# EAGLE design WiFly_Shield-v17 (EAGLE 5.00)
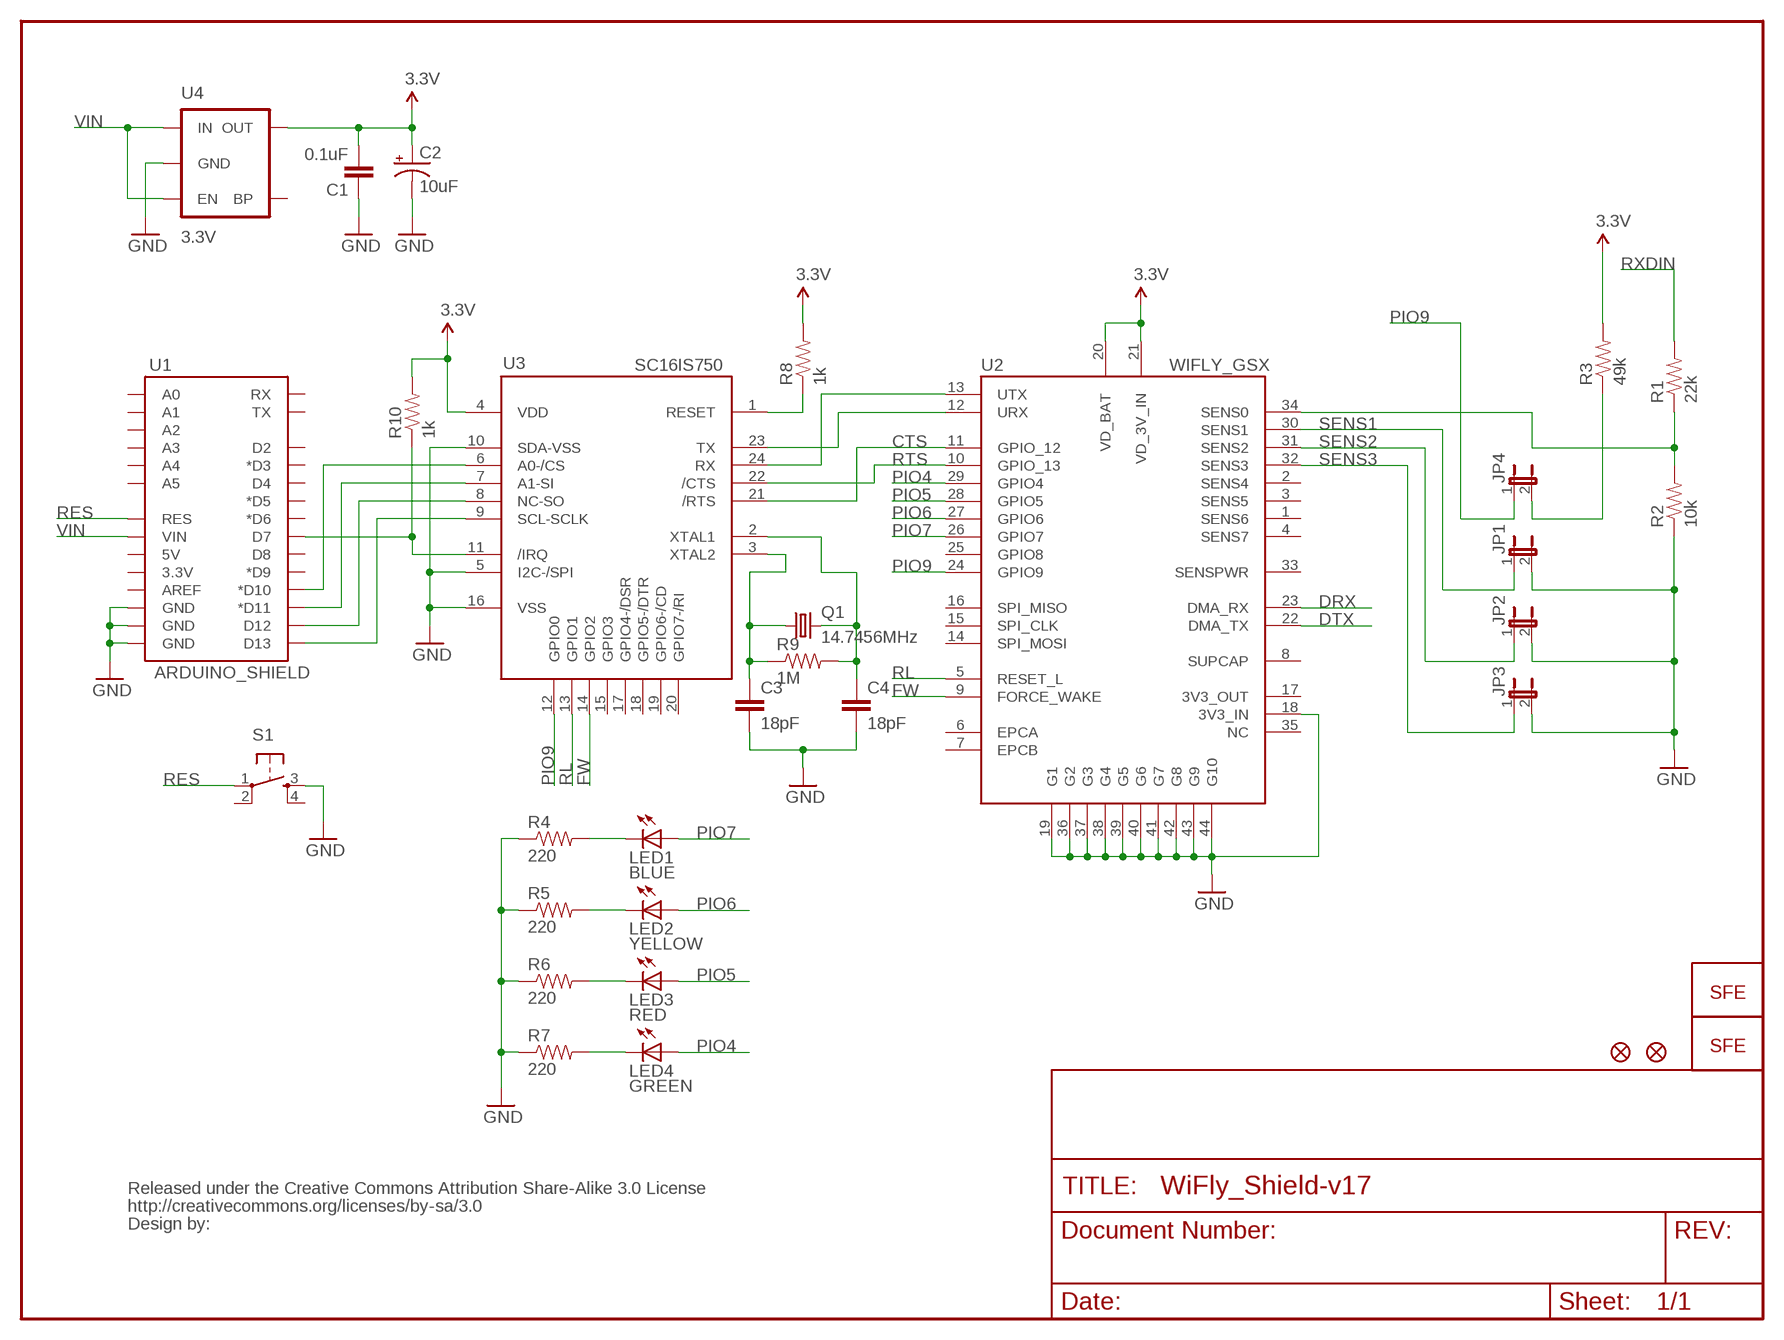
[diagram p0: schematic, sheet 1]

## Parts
C1  0.1uF  CAP0402-CAP  [0402-CAP]
C2  10uF  CAP_POL1206  [EIA3216]
C3  18pF  CAP0402-CAP  [0402-CAP]
C4  18pF  CAP0402-CAP  [0402-CAP]
JP1  JUMPER-2SMD-NO  [SJ_2S-NO]
JP2  JUMPER-2SMD-NO  [SJ_2S-NO]
JP3  JUMPER-2SMD-NO  [SJ_2S-NO]
JP4  JUMPER-2SMD-NO  [SJ_2S-NO]
JP6  LOGO-SFENEW  [SFE-NEW-WEBLOGO]
JP7  FIDUCIAL1X2  [FIDUCIAL-1X2]
JP8  FIDUCIAL1X2  [FIDUCIAL-1X2]
JP9  LOGO-SFESK  [SFE-LOGO-FLAME]
LED1  BLUE  LED0603  [LED-0603]
LED2  YELLOW  LED0603  [LED-0603]
LED3  RED  LED0603  [LED-0603]
LED4  GREEN  LED0603  [LED-0603]
Q1  14.7456MHz  CRYSTAL5X3  [CRYSTAL-SMD-5X3]
R1  22k  RESISTOR0402-RES  [0402-RES]
R2  10k  RESISTOR0402-RES  [0402-RES]
R3  49k  RESISTOR0402-RES  [0402-RES]
R4  220  RESISTOR0402-RES  [0402-RES]
R5  220  RESISTOR0402-RES  [0402-RES]
R6  220  RESISTOR0402-RES  [0402-RES]
R7  220  RESISTOR0402-RES  [0402-RES]
R8  1k  RESISTOR0402-RES  [0402-RES]
R9  1M  RESISTOR0402-RES  [0402-RES]
R10  1k  RESISTOR0402-RES  [0402-RES]
S1  TAC_SWITCHSMD  [TACTILE_SWITCH_SMD]
U1  ARDUINO_SHIELD  ARDUINO_SHIELDLABEL  [DUEMILANOVE_SHIELD]
U2  WIFLY_GSX  [WIFLY_GSX]
U3  SC16IS750  [QFN-24]
U4  3.3V  V_REG_LDOSMD  [SOT23-5]
U$1  CREATIVE_COMMONS  [CREATIVE_COMMONS]

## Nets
3.3V: C1.2 C2.A(+) R3.2 R8.2 R10.2 U2.20(VD_BAT) U2.21(VD_3V_IN) U3.4(VDD) U4.5(OUT)
CTS: U2.11(GPIO_12) U3.21(/RTS)
DRX: U2.23(DMA_RX)
DTX: U2.22(DMA_TX)
FW: U2.9(FORCE_WAKE) U3.14(GPIO2)
GND: C1.1 C2.C(-) C3.2 C4.2 JP1.2 JP2.2 JP3.2 R2.1 R4.1 R5.1 R6.1 R7.1 S1.3 U1.GND@0(GND) U1.GND@1(GND) U1.GND@2(GND) U2.18(3V3_IN) U2.19(G1) U2.36(G2) U2.37(G3) U2.38(G4) U2.39(G5) U2.40(G6) U2.41(G7) U2.42(G8) U2.43(G9) U2.44(G10) U3.5(I2C-/SPI) U3.10(SDA-VSS) U3.16(VSS) U4.2(GND)
N$1: LED4.C R7.2
N$2: JP4.2 R3.1
N$3: LED3.C R6.2
N$4: LED2.C R5.2
N$5: LED1.C R4.2
N$6: U2.13(UTX) U3.24(RX)
N$7: U2.12(URX) U3.23(TX)
N$8: U1.D10(*D10) U3.6(A0-/CS)
N$9: R8.1 U3.1(RESET)
N$10: U1.D11(*D11) U3.7(A1-SI)
N$11: C3.1 Q1.1 R9.1 U3.3(XTAL2)
N$12: C4.1 Q1.3 R9.2 U3.2(XTAL1)
N$13: U1.D12 U3.8(NC-SO)
N$14: U1.D13 U3.9(SCL-SCLK)
N$16: R1.1 R2.2 U2.34(SENS0)
N$154: R10.1 U1.D7 U3.11(/IRQ)
PIO4: LED4.A U2.29(GPIO4)
PIO5: LED3.A U2.28(GPIO5)
PIO6: LED2.A U2.27(GPIO6)
PIO7: LED1.A U2.26(GPIO7)
PIO9: JP4.1 U2.24(GPIO9) U3.12(GPIO0)
RES: S1.1 U1.RES
RL: U2.5(RESET_L) U3.13(GPIO1)
RTS: U2.10(GPIO_13) U3.22(/CTS)
RXDIN: R1.2
SENS1: JP1.1 U2.30(SENS1)
SENS2: JP2.1 U2.31(SENS2)
SENS3: JP3.1 U2.32(SENS3)
VIN: U1.VIN U4.1(IN) U4.3(EN)
Unconnected: S1.2 S1.4 U1.3.3V U1.5V U1.A0 U1.A1 U1.A2 U1.A3 U1.A4 U1.A5 U1.AREF U1.D2 U1.D3(*D3) U1.D4 U1.D5(*D5) U1.D6(*D6) U1.D8 U1.D9(*D9) U1.RX U1.TX U2.1(SENS6) U2.2(SENS4) U2.3(SENS5) U2.4(SENS7) U2.6(EPCA) U2.7(EPCB) U2.8(SUPCAP) U2.14(SPI_MOSI) U2.15(SPI_CLK) U2.16(SPI_MISO) U2.17(3V3_OUT) U2.25(GPIO8) U2.33(SENSPWR) U2.35(NC) U3.15(GPIO3) U3.17(GPIO4-/DSR) U3.18(GPIO5-/DTR) U3.19(GPIO6-/CD) U3.20(GPIO7-/RI) U4.4(BP)

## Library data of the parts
C1 C3 C4 = SparkFun:CAP: Capacitor
C2 = SparkFun:CAP_POL: Capacitor Polarized
JP1-JP4 = SparkFun:JUMPER-2: Jumper
JP6 JP9 = SparkFun:LOGO-SFE: Spark Fun Electronics PCB Logo
JP7 JP8 = SparkFun:FIDUCIAL: Fiducial Alignment Points
LED1-LED4 = SparkFun:LED: LEDs
Q1 = SparkFun:CRYSTAL: Crystals
R1-R10 = SparkFun:RESISTOR: Resistor
S1 = SparkFun:TAC_SWITCH: Momentary Switch Button commonly used for reset or general input. Spark Fun Electronics SKU : COM-00097
U1 = SparkFun:ARDUINO_SHIELD
U2 = SparkFun:WIFLY_GSX
U3 = SparkFun:SC16IS750
U4 = SparkFun:V_REG_LDO: Voltage Regulator LDO Standard 150mA LDO voltage regulator in SOT-23 layout. Micrel part MIC5205. BP (by-pass) pin is used to lower output noise with 470pF cap.
U$1 = SparkFun:CREATIVE_COMMONS

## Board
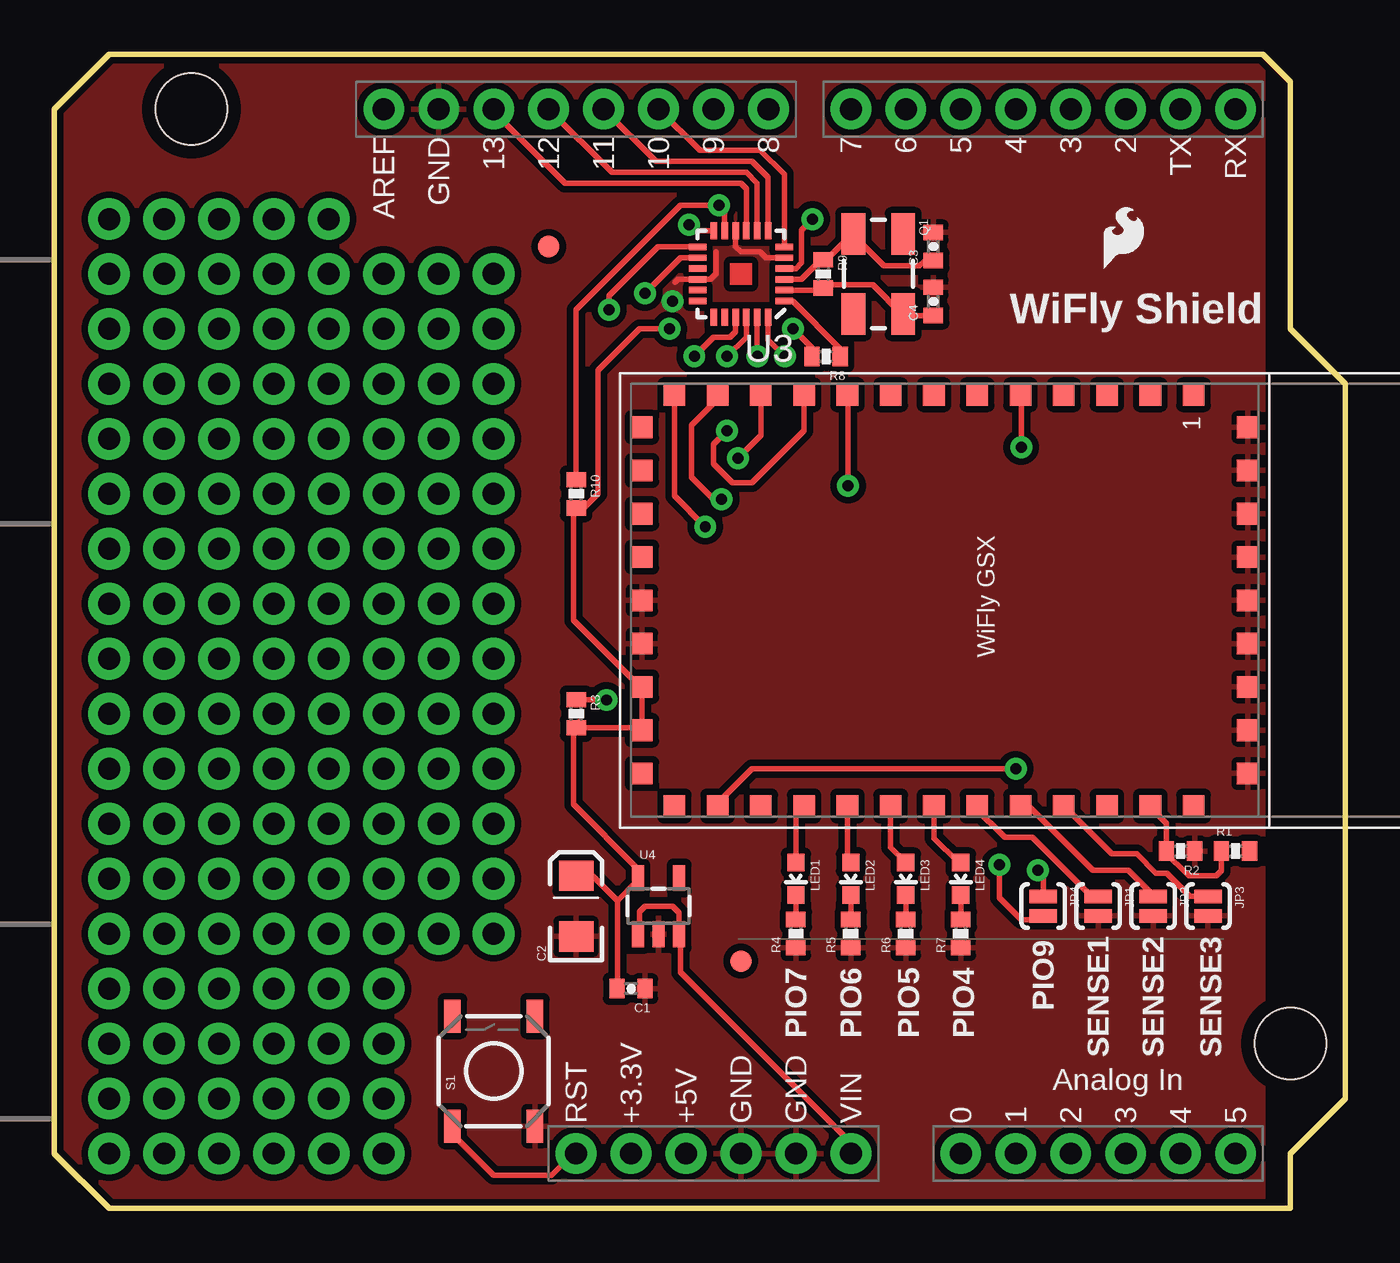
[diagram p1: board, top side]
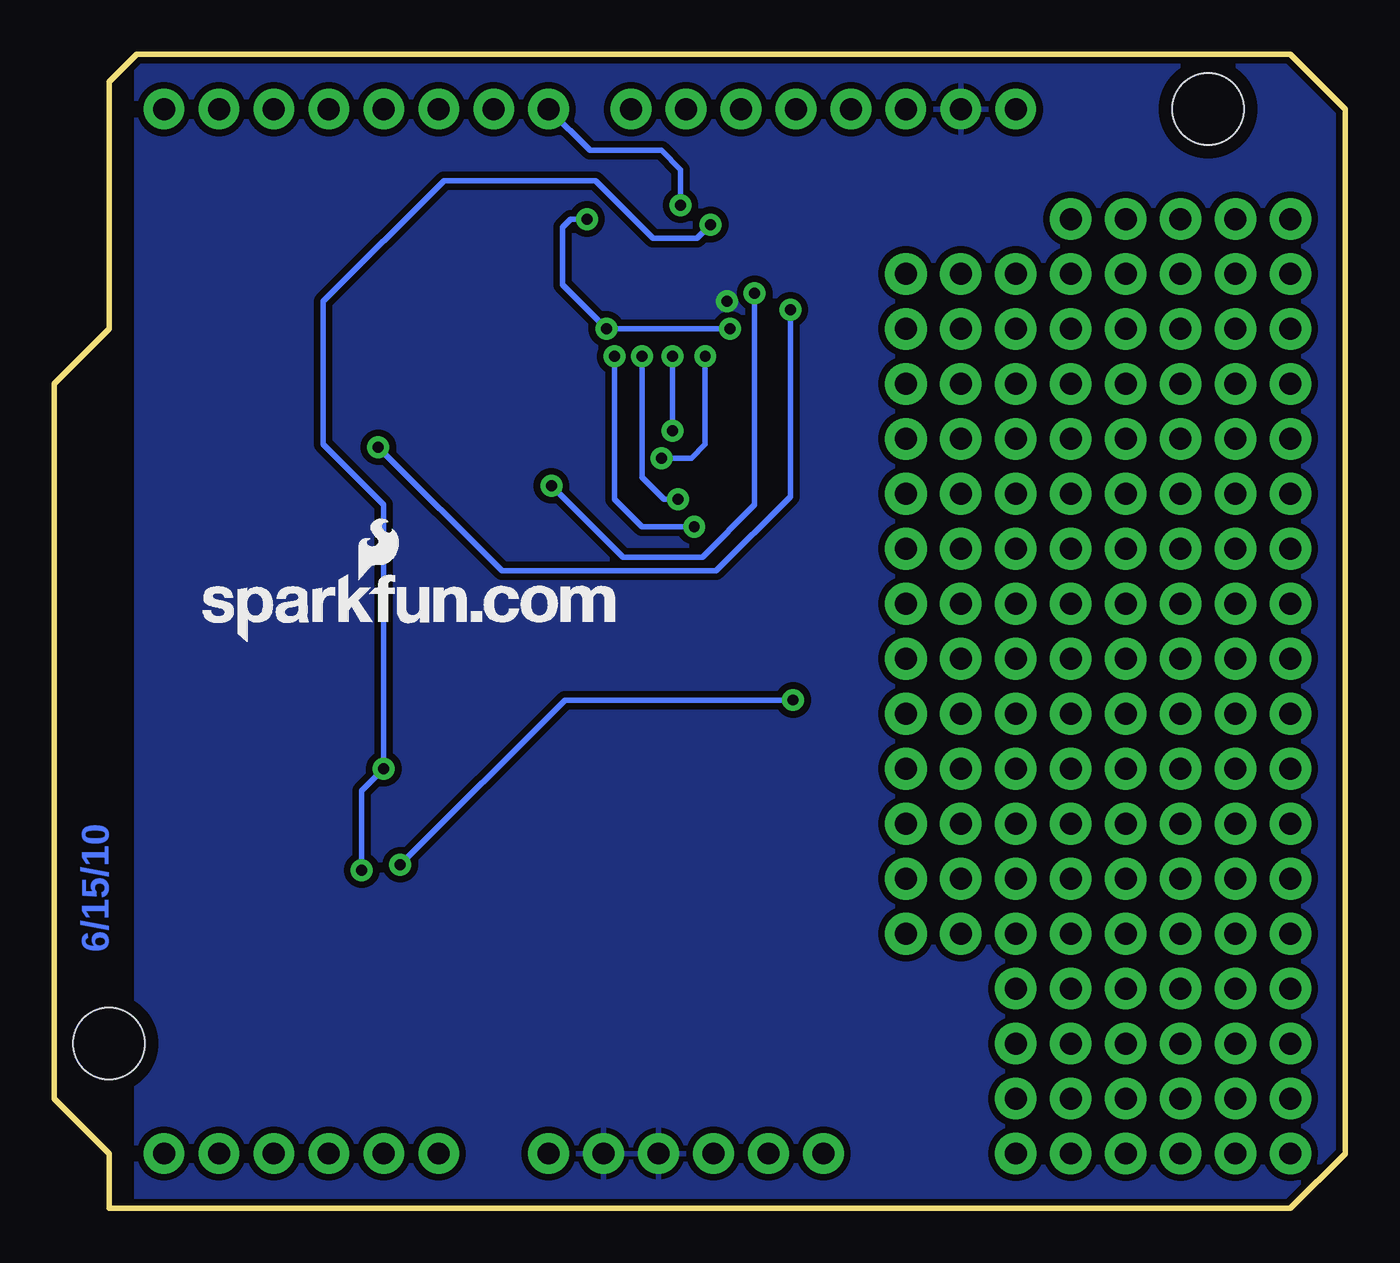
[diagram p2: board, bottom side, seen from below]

Size 59.69 x 53.34 mm. Coordinates in mm from the lower left corner, seen from the top.
Outline: 2.54,53.34 55.88,53.34 57.15,52.07 57.15,40.64 59.69,38.1 59.69,5.08 57.15,2.54 57.15,0 2.54,0 0,2.54 0,50.8 2.54,53.34
Copper layers (1*16): Top 0.035mm / dielectric 1.5mm / Bottom 0.035mm
Design rules "SparkFun *": minimum track width 8mil, minimum drill 20mil, track to track 8mil, track to pad 8mil, pad to pad 7mil, via to via 8mil, smd to smd 8mil, copper to edge 10mil, drill to drill 8mil, minimum pad ring 12mil, minimum via ring 10mil, stop-mask expansion 4mil, vias tented up to drill 25mil, thermal gap 10mil

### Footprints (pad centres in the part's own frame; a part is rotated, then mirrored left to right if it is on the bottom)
0402-CAP = smd 0.7 x 0.9: 1 -0.65,0; 2 0.65,0
EIA3216 = smd 1.4 x 1.6: A 1.4,0; C -1.4,0
SJ_2S-NO = smd 0.635 x 1.27: 1 -0.45,0; 2 0.45,0
FIDUCIAL-1X2 = smd 1 x 1: 1 0,0
LED-0603 = smd 0.8 x 0.8: A 0,-0.75; C 0,0.75
CRYSTAL-SMD-5X3 = smd 1.9 x 1.1: 1 -1.85,-1.15; 2 1.85,-1.15; 3 1.85,1.15; 4 -1.85,1.15
0402-RES = smd 0.7 x 0.9: 1 -0.65,0; 2 0.65,0
TACTILE_SWITCH_SMD = smd 1.524 x 0.762: 1 -2.54,1.905; 2 2.54,1.905; 3 -2.54,-1.905; 4 2.54,-1.905
DUEMILANOVE_SHIELD = drill 1.016 pad 1.88 round: 3.3V 50.8,26.67; 5V 50.8,29.21; A0 50.8,41.91; A1 50.8,44.45; A2 50.8,46.99; A3 50.8,49.53; A4 50.8,52.07; A5 50.8,54.61; AREF 2.54,15.24; D2 2.54,49.53; D3 2.54,46.99; D4 2.54,44.45; D5 2.54,41.91; D6 2.54,39.37; D7 2.54,36.83; D8 2.54,33.02; D9 2.54,30.48; D10 2.54,27.94; D11 2.54,25.4; D12 2.54,22.86; D13 2.54,20.32; GND@0 50.8,31.75; GND@1 50.8,34.29; GND@2 2.54,17.78; RES 50.8,24.13; RX 2.54,54.61; TX 2.54,52.07; VIN 50.8,36.83 | hole 3.302: 45.72,57.15; 2.54,6.35
WIFLY_GSX = smd 1 x 1: 1 0.5,26; 2 0.5,24; 3 0.5,22; 4 0.5,20; 5 0.5,18; 6 0.5,16; 7 0.5,14; 8 0.5,12; 9 0.5,10; 10 0.5,8; 11 0.5,6; 12 0.5,4; 13 0.5,2; 14 2,0.5; 15 4,0.5; 16 6,0.5; 17 8,0.5; 18 10,0.5; 19 12,0.5; 20 14,0.5; 21 16,0.5; 22 18,0.5; 23 19.5,2; 24 19.5,4; 25 19.5,6; 26 19.5,8; 27 19.5,10; 28 19.5,12; 29 19.5,14; 30 19.5,16; 31 19.5,18; 32 19.5,20; 33 19.5,22; 34 19.5,24; 35 19.5,26; 36 18,28.5; 37 16,28.5; 38 14,28.5; 39 12,28.5; 40 10,28.5; 41 8,28.5; 42 6,28.5; 43 4,28.5; 44 2,28.5
QFN-24 = smd 0.8 x 0.3: 1 -2,1.25; 2 -2,0.75; 3 -2,0.25; 4 -2,-0.25; 5 -2,-0.75; 6 -2,-1.25; 13 2,-1.25; 14 2,-0.75; 15 2,-0.25; 16 2,0.25; 17 2,0.75; 18 2,1.25 | smd 0.3 x 0.8: 7 -1.25,-2; 8 -0.75,-2; 9 -0.25,-2; 10 0.25,-2; 11 0.75,-2; 12 1.25,-2; 19 1.25,2; 20 0.75,2; 21 0.25,2; 22 -0.25,2; 23 -0.75,2; 24 -1.25,2
SOT23-5 = smd 0.55 x 1.2: 1 -0.95,-1.3; 2 0,-1.3; 3 0.95,-1.3; 4 0.95,1.3; 5 -0.95,1.3

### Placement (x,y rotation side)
C1  26.67,10.16 180 top
C2  24.13,13.97 90 top
C3  40.64,44.45 90 top
C4  40.64,41.91 90 top
JP1  48.26,13.97 270 top
JP2  50.8,13.97 270 top
JP3  53.34,13.97 270 top
JP4  45.72,13.97 270 top
JP6  52.83,26.16 0 bottom
JP7  31.75,11.43 0 top
JP8  22.86,44.45 0 top
JP9  48.51,43.43 0 top
LED1  34.29,15.24 180 top
LED2  36.83,15.24 180 top
LED3  39.37,15.24 180 top
LED4  41.91,15.24 180 top
Q1  38.1,43.18 270 top
R1  54.61,16.51 0 top
R2  52.07,16.51 180 top
R3  24.13,22.86 270 top
R4  34.29,12.7 90 top
R5  36.83,12.7 90 top
R6  39.37,12.7 90 top
R7  41.91,12.7 90 top
R8  35.69,39.37 180 top
R9  35.56,43.18 270 top
R10  24.13,33.02 270 top
S1  20.32,6.35 90 top
U1  0,53.34 270 top
U2  26.67,38.1 270 top
U3  31.75,43.18 180 top
U4  27.94,13.97 0 top
U$1  not placed on the board

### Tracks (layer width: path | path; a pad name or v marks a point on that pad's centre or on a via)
3.3V  (via drill 0.51)
  Top 0.254: 27.11,22.16 27.07,22.21 24.37,22.21 24.26,22.1 24.14,22.21 R3.2 24.13,22.1 24,22.1 | 27.11,22.16 U2.21 | 24,22.1 24,18.67 26.99,15.68 26.99,15.31 26.95,15.27 | 24,22.1 24,22.23 24.26,22.48 | 27.3,22.1 | 27.3,22.1 U2.21 27.17,22.22 | 27.18,22.23 27.3,22.1 | 27.18,22.23 27.17,22.23 U2.20 27.17,24.12 | v34.16,40.64 35.04,39.77 35.04,39.38 35.05,39.37 R8.2 | v35.05,45.72 34.54,45.21 34.54,43.69 34.29,43.43 33.79,43.43 33.78,43.43 U3.4 | 24.14,32.37 24.13,32.38 24,32.26 24,27.18 27.08,24.1 27.15,24.1 27.17,24.12 | 24.14,32.37 24.5,32.37 25.15,33.02 25.15,38.73 27.05,40.64 v28.45,40.64 | 27.17,24.12 27.18,24.13 | C1.2 26.04,10.18 26.04,14.22 | 26.92,15.24 26.96,15.24 U4.5 26.95,15.27 | 26.04,14.22 26.92,15.11 26.92,15.24 | C2.A 24.89,15.37 26.04,14.22 | 26.92,15.24 26.95,15.27 | 27.11,22.16 27.17,22.22 | 27.17,22.22 27.18,22.23 | R10.2 24.13,32.26 24.14,32.27 24.14,32.37
  Bottom 0.254: v35.05,45.72 35.81,45.72 36.2,45.34 36.2,42.67 v34.16,40.64 v28.45,40.64
CTS  (via drill 0.51)
  Top 0.254: U3.21 31.5,40.52 31.24,40.26 30.48,40.26 v29.59,39.37 | U2.11 32.67,35.72 v31.62,34.67
  Bottom 0.254: v31.62,34.67 30.23,34.67 29.59,35.31 v29.59,39.37
FW  (via drill 0.51)
  Top 0.254: U3.14 28.94,43.93 v27.3,42.29 | v36.7,33.4 36.7,37.57 U2.9
  Bottom 0.254: v27.3,42.29 27.3,32.51 29.72,30.1 33.4,30.1 v36.7,33.4
GND  (via drill 0.51)
  Top 0.254: 30.61,44.2 30.61,43.18 30.35,42.93 29.84,42.93 U3.16 28.83,42.93 28.7,42.8 | U3.5 32.91,43.93 32.64,44.2 31.75,44.2 31.5,44.45 U3.10
  other vias: 28.57,41.91
  pour Bottom (isolate 0.305): 2.54,53.34 55.88,53.34 55.88,0 2.54,0 0,2.54 0,50.8
  pour Top (isolate 0.305): 2.54,53.34 55.88,53.34 55.88,0 2.54,0 0,2.54 0,50.8
N$1
  Top 0.254: 41.91,14.61 LED4.C R7.2
N$2  (via drill 0.51)
  Top 0.254: R3.1 25.51,23.51 v25.53,23.5 | v43.69,15.88 43.69,14.35 44.7,13.34 45.47,13.34 45.65,13.52 JP4.2
  Bottom 0.254: v25.53,23.5 36.07,23.5 v43.69,15.88
N$3
  Top 0.254: 39.37,14.61 LED3.C R6.2
N$4
  Top 0.254: 36.83,14.61 LED2.C R5.2
N$5
  Top 0.254: R4.2 LED1.C
N$6  (via drill 0.51)
  Top 0.254: U3.24 33,40.15 v33.78,39.37 | U2.13 28.67,32.92 v30.1,31.5
  Bottom 0.254: v30.1,31.5 32.51,31.5 33.78,32.77 v33.78,39.37
N$7  (via drill 0.51)
  Top 0.254: U3.23 32.5,39.89 v32.51,39.37 | U2.12 30.67,37.4 29.46,36.2 29.46,33.78 30.48,32.77 v30.86,32.77
  Bottom 0.254: v30.86,32.77 31.5,32.77 32.51,33.78 v32.51,39.37
N$8
  Top 0.254: U1.D10 29.84,48.9 32.64,48.9 33.75,47.78 U3.6
N$9
  Top 0.254: R8.1 36.34,39.74 34.14,41.93 U3.1
N$10
  Top 0.254: U3.7 33,47.65 32.26,48.39 27.81,48.39 U1.D11
N$11
  Top 0.254: C3.1 40.24,43.8 40.01,43.56 38.35,43.56 36.95,44.97 | 36.95,44.97 Q1.1 | 36.95,44.97 36.84,44.97 35.69,43.81 35.67,43.83 R9.1 35.45,43.83 34.55,42.93 U3.3
N$12
  Top 0.254: C4.1 39.38,41.26 39.31,41.33 Q1.3 39.19,41.33 37.85,42.67 35.81,42.67 35.56,42.42 R9.2 35.56,42.55 35.45,42.43 U3.2
N$13
  Top 0.254: U3.8 32.5,47.38 32,47.88 25.78,47.88 U1.D12
N$14
  Top 0.254: U3.9 32,47.12 31.75,47.37 23.62,47.37 20.32,50.67 U1.D13
N$15  (via drill 1.02 pad 1.93)
  other vias: 5.08,2.54
N$16
  Top 0.254: U2.34 50.67,18.55 51.42,17.8 R2.2 51.31,16.51 52.45,15.37 53.72,15.37 53.96,15.61 R1.1
N$17  (via drill 1.02 pad 1.93)
  other vias: 7.62,2.54
N$18  (via drill 1.02 pad 1.93)
  other vias: 10.16,2.54
N$19  (via drill 1.02 pad 1.93)
  other vias: 12.7,2.54
N$20  (via drill 1.02 pad 1.93)
  other vias: 15.24,2.54
N$23  (via drill 1.02 pad 1.93)
  other vias: 2.54,2.54
N$24  (via drill 1.02 pad 1.93)
  other vias: 5.08,5.08
N$25  (via drill 1.02 pad 1.93)
  other vias: 7.62,5.08
N$26  (via drill 1.02 pad 1.93)
  other vias: 10.16,5.08
N$27  (via drill 1.02 pad 1.93)
  other vias: 12.7,5.08
N$28  (via drill 1.02 pad 1.93)
  other vias: 15.24,5.08
N$31  (via drill 1.02 pad 1.93)
  other vias: 2.54,5.08
N$32  (via drill 1.02 pad 1.93)
  other vias: 5.08,7.62
N$33  (via drill 1.02 pad 1.93)
  other vias: 7.62,7.62
N$34  (via drill 1.02 pad 1.93)
  other vias: 10.16,7.62
N$35  (via drill 1.02 pad 1.93)
  other vias: 12.7,7.62
N$36  (via drill 1.02 pad 1.93)
  other vias: 15.24,7.62
N$39  (via drill 1.02 pad 1.93)
  other vias: 2.54,7.62
N$40  (via drill 1.02 pad 1.93)
  other vias: 5.08,10.16
N$41  (via drill 1.02 pad 1.93)
  other vias: 7.62,10.16
N$42  (via drill 1.02 pad 1.93)
  other vias: 10.16,10.16
N$43  (via drill 1.02 pad 1.93)
  other vias: 12.7,10.16
N$44  (via drill 1.02 pad 1.93)
  other vias: 15.24,10.16
N$47  (via drill 1.02 pad 1.93)
  other vias: 2.54,10.16
N$48  (via drill 1.02 pad 1.93)
  other vias: 5.08,12.7
N$49  (via drill 1.02 pad 1.93)
  other vias: 7.62,12.7
N$50  (via drill 1.02 pad 1.93)
  other vias: 10.16,12.7
N$51  (via drill 1.02 pad 1.93)
  other vias: 12.7,12.7
N$52  (via drill 1.02 pad 1.93)
  other vias: 15.24,12.7
N$53  (via drill 1.02 pad 1.93)
  other vias: 17.78,12.7
N$54  (via drill 1.02 pad 1.93)
  other vias: 20.32,12.7
N$55  (via drill 1.02 pad 1.93)
  other vias: 2.54,12.7
N$56  (via drill 1.02 pad 1.93)
  other vias: 5.08,15.24
N$57  (via drill 1.02 pad 1.93)
  other vias: 7.62,15.24
N$58  (via drill 1.02 pad 1.93)
  other vias: 10.16,15.24
N$59  (via drill 1.02 pad 1.93)
  other vias: 12.7,15.24
N$60  (via drill 1.02 pad 1.93)
  other vias: 15.24,15.24
N$61  (via drill 1.02 pad 1.93)
  other vias: 17.78,15.24
N$62  (via drill 1.02 pad 1.93)
  other vias: 20.32,15.24
N$63  (via drill 1.02 pad 1.93)
  other vias: 2.54,15.24
N$64  (via drill 1.02 pad 1.93)
  other vias: 5.08,17.78
N$65  (via drill 1.02 pad 1.93)
  other vias: 7.62,17.78
N$66  (via drill 1.02 pad 1.93)
  other vias: 10.16,17.78
N$67  (via drill 1.02 pad 1.93)
  other vias: 12.7,17.78
N$68  (via drill 1.02 pad 1.93)
  other vias: 15.24,17.78
N$69  (via drill 1.02 pad 1.93)
  other vias: 17.78,17.78
N$70  (via drill 1.02 pad 1.93)
  other vias: 20.32,17.78
N$71  (via drill 1.02 pad 1.93)
  other vias: 2.54,17.78
N$72  (via drill 1.02 pad 1.93)
  other vias: 5.08,20.32
N$73  (via drill 1.02 pad 1.93)
  other vias: 7.62,20.32
N$74  (via drill 1.02 pad 1.93)
  other vias: 10.16,20.32
N$75  (via drill 1.02 pad 1.93)
  other vias: 12.7,20.32
N$76  (via drill 1.02 pad 1.93)
  other vias: 15.24,20.32
N$77  (via drill 1.02 pad 1.93)
  other vias: 17.78,20.32
N$78  (via drill 1.02 pad 1.93)
  other vias: 20.32,20.32
N$79  (via drill 1.02 pad 1.93)
  other vias: 2.54,20.32
N$80  (via drill 1.02 pad 1.93)
  other vias: 5.08,22.86
N$81  (via drill 1.02 pad 1.93)
  other vias: 7.62,22.86
N$82  (via drill 1.02 pad 1.93)
  other vias: 10.16,22.86
N$83  (via drill 1.02 pad 1.93)
  other vias: 12.7,22.86
N$84  (via drill 1.02 pad 1.93)
  other vias: 15.24,22.86
N$85  (via drill 1.02 pad 1.93)
  other vias: 17.78,22.86
N$86  (via drill 1.02 pad 1.93)
  other vias: 20.32,22.86
N$87  (via drill 1.02 pad 1.93)
  other vias: 2.54,22.86
N$88  (via drill 1.02 pad 1.93)
  other vias: 5.08,25.4
N$89  (via drill 1.02 pad 1.93)
  other vias: 7.62,25.4
N$90  (via drill 1.02 pad 1.93)
  other vias: 10.16,25.4
N$91  (via drill 1.02 pad 1.93)
  other vias: 12.7,25.4
N$92  (via drill 1.02 pad 1.93)
  other vias: 15.24,25.4
N$93  (via drill 1.02 pad 1.93)
  other vias: 17.78,25.4
N$94  (via drill 1.02 pad 1.93)
  other vias: 20.32,25.4
N$95  (via drill 1.02 pad 1.93)
  other vias: 2.54,25.4
N$96  (via drill 1.02 pad 1.93)
  other vias: 5.08,27.94
N$97  (via drill 1.02 pad 1.93)
  other vias: 7.62,27.94
N$98  (via drill 1.02 pad 1.93)
  other vias: 10.16,27.94
N$99  (via drill 1.02 pad 1.93)
  other vias: 12.7,27.94
N$100  (via drill 1.02 pad 1.93)
  other vias: 15.24,27.94
N$101  (via drill 1.02 pad 1.93)
  other vias: 17.78,27.94
N$102  (via drill 1.02 pad 1.93)
  other vias: 20.32,27.94
N$103  (via drill 1.02 pad 1.93)
  other vias: 2.54,27.94
N$104  (via drill 1.02 pad 1.93)
  other vias: 5.08,30.48
N$105  (via drill 1.02 pad 1.93)
  other vias: 7.62,30.48
N$106  (via drill 1.02 pad 1.93)
  other vias: 10.16,30.48
N$107  (via drill 1.02 pad 1.93)
  other vias: 12.7,30.48
N$108  (via drill 1.02 pad 1.93)
  other vias: 15.24,30.48
N$109  (via drill 1.02 pad 1.93)
  other vias: 17.78,30.48
N$110  (via drill 1.02 pad 1.93)
  other vias: 20.32,30.48
N$111  (via drill 1.02 pad 1.93)
  other vias: 2.54,30.48
N$112  (via drill 1.02 pad 1.93)
  other vias: 5.08,33.02
N$113  (via drill 1.02 pad 1.93)
  other vias: 7.62,33.02
N$114  (via drill 1.02 pad 1.93)
  other vias: 10.16,33.02
N$115  (via drill 1.02 pad 1.93)
  other vias: 12.7,33.02
N$116  (via drill 1.02 pad 1.93)
  other vias: 15.24,33.02
N$117  (via drill 1.02 pad 1.93)
  other vias: 17.78,33.02
N$118  (via drill 1.02 pad 1.93)
  other vias: 20.32,33.02
N$119  (via drill 1.02 pad 1.93)
  other vias: 2.54,33.02
N$120  (via drill 1.02 pad 1.93)
  other vias: 5.08,35.56
N$121  (via drill 1.02 pad 1.93)
  other vias: 7.62,35.56
N$122  (via drill 1.02 pad 1.93)
  other vias: 10.16,35.56
N$123  (via drill 1.02 pad 1.93)
  other vias: 12.7,35.56
N$124  (via drill 1.02 pad 1.93)
  other vias: 15.24,35.56
N$125  (via drill 1.02 pad 1.93)
  other vias: 17.78,35.56
N$126  (via drill 1.02 pad 1.93)
  other vias: 20.32,35.56
N$127  (via drill 1.02 pad 1.93)
  other vias: 2.54,35.56
N$128  (via drill 1.02 pad 1.93)
  other vias: 5.08,38.1
N$129  (via drill 1.02 pad 1.93)
  other vias: 7.62,38.1
N$130  (via drill 1.02 pad 1.93)
  other vias: 10.16,38.1
N$131  (via drill 1.02 pad 1.93)
  other vias: 12.7,38.1
N$132  (via drill 1.02 pad 1.93)
  other vias: 15.24,38.1
N$133  (via drill 1.02 pad 1.93)
  other vias: 17.78,38.1
N$134  (via drill 1.02 pad 1.93)
  other vias: 20.32,38.1
N$135  (via drill 1.02 pad 1.93)
  other vias: 2.54,38.1
N$136  (via drill 1.02 pad 1.93)
  other vias: 5.08,40.64
N$137  (via drill 1.02 pad 1.93)
  other vias: 7.62,40.64
N$138  (via drill 1.02 pad 1.93)
  other vias: 10.16,40.64
N$139  (via drill 1.02 pad 1.93)
  other vias: 12.7,40.64
N$140  (via drill 1.02 pad 1.93)
  other vias: 15.24,40.64
N$141  (via drill 1.02 pad 1.93)
  other vias: 17.78,40.64
N$142  (via drill 1.02 pad 1.93)
  other vias: 20.32,40.64
N$143  (via drill 1.02 pad 1.93)
  other vias: 2.54,40.64
N$144  (via drill 1.02 pad 1.93)
  other vias: 5.08,43.18
N$145  (via drill 1.02 pad 1.93)
  other vias: 7.62,43.18
N$146  (via drill 1.02 pad 1.93)
  other vias: 10.16,43.18
N$147  (via drill 1.02 pad 1.93)
  other vias: 12.7,43.18
N$148  (via drill 1.02 pad 1.93)
  other vias: 15.24,43.18
N$149  (via drill 1.02 pad 1.93)
  other vias: 17.78,43.18
N$150  (via drill 1.02 pad 1.93)
  other vias: 20.32,43.18
N$151  (via drill 1.02 pad 1.93)
  other vias: 2.54,43.18
N$152  (via drill 1.02 pad 1.93)
  other vias: 5.08,45.72
N$153  (via drill 1.02 pad 1.93)
  other vias: 7.62,45.72
N$154  (via drill 0.51)
  Top 0.254: U3.11 31,46.09 v30.73,46.35 28.96,46.35 24.13,41.53 R10.1
  Bottom 0.254: v30.73,46.35 30.73,48.01 31.62,48.9 34.92,48.9 U1.D7
N$155  (via drill 1.02 pad 1.93)
  other vias: 10.16,45.72
N$156  (via drill 1.02 pad 1.93)
  other vias: 12.7,45.72
N$160  (via drill 1.02 pad 1.93)
  other vias: 2.54,45.72
PIO4
  Top 0.254: LED4.A 41.8,15.99 40.67,17.11 U2.29
PIO5
  Top 0.254: LED3.A 39.37,16 38.67,16.7 U2.28
PIO6
  Top 0.254: LED2.A 36.95,15.99 36.96,16 36.67,16.29 U2.27
PIO7
  Top 0.254: U2.26 34.67,18.54 34.29,18.16 LED1.A
PIO9  (via drill 0.51)
  Top 0.254: JP4.1 45.72,15.37 v45.47,15.62 | U2.24 30.67,18.73 32.26,20.32 43.18,20.32 v44.45,20.32 | U3.12 29.62,45.18 v29.34,45.47
  Bottom 0.254: v45.47,15.62 45.47,19.3 v44.45,20.32 44.45,32.51 47.24,35.31 47.24,41.91 41.66,47.5 34.67,47.5 32,44.83 29.97,44.83 v29.34,45.47
RES
  Top 0.254: U1.RES 24,2.54 22.99,1.52 20.32,1.52 18.41,3.43 S1.1
RL  (via drill 0.51)
  Top 0.254: U3.13 27.92,44.43 25.65,42.16 v25.65,41.53 | v44.7,35.18 44.7,37.57 U2.5
  Bottom 0.254: v25.65,41.53 25.65,32.89 29.08,29.46 38.99,29.46 v44.7,35.18
RTS  (via drill 0.51)
  Top 0.254: U3.22 32,40.26 v31.11,39.37 | U2.10 34.67,35.94 32.26,33.53 31.37,33.53 30.48,34.42 30.48,35.31 v31.11,35.94
  Bottom 0.254: 31.11,36.2 31.11,36.07 | 31.11,36.2 v31.11,39.37 | v31.11,35.94 31.11,36.2
SENS1
  Top 0.254: JP1.1 47.94,14.42 45.21,17.14 43.94,17.14 42.55,18.54 42.6,18.6 U2.30
SENS2
  Top 0.254: JP2.1 50.8,14.48 49.66,15.62 48.01,15.62 45.03,18.6 U2.31
SENS3
  Top 0.254: JP3.1 52.51,14.42 51.44,15.49 50.93,15.49 50.04,16.38 48.9,16.38 U2.32 | U2.32 46.61,18.67 | U2.32
VIN
  Top 0.254: U1.VIN 36.83,3.05 28.96,10.92 28.96,12.6 U4.3 28.89,13.65 28.57,13.97 27.3,13.97 27.05,13.72 27.05,12.7 27.02,12.67 U4.1

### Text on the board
Bottom: 6/15/10
tPlace: WiFly Shield | PIO9 | PIO7 | PIO6 | PIO5 | PIO4 | SENSE1 | SENSE2 | SENSE3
